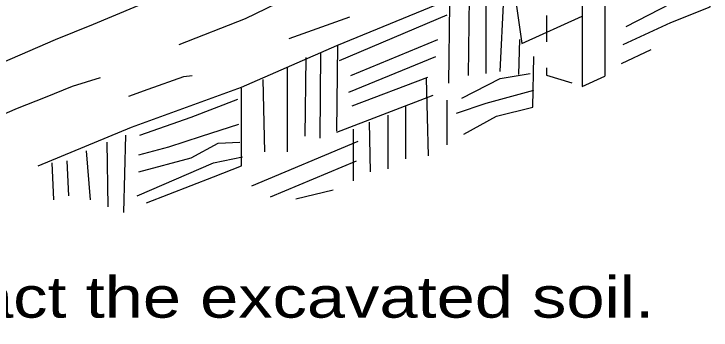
# Model space of a CAD drawing. Extents: x 1083.1 to 1117.1, y 672.5 to 716.5.
# Drawn here: x 1109.933 to 1112.582, y 688.724 to 689.926 of the extents above; entities that cross this region are included whole.
import ezdxf
from ezdxf.enums import TextEntityAlignment as Align

# ---------------------------------------------------------------- set-up
doc = ezdxf.new("R2010")
doc.units = 0
doc.header["$LTSCALE"] = 0.062
doc.linetypes.add('DOTTED', pattern=[1.5, 0.3, -1.2])
doc.layers.add('1', color=7, linetype='Continuous', lineweight=13)

msp = doc.modelspace()

# ---------------------------------------------------------------- linework, layer by layer
at = {"layer": '1', "lineweight": 25}
for p, q in [((1112.17775, 692.14508), (1112.17775, 689.6895)), ((1112.09242, 692.13417), (1112.09242, 689.65067)), ((1111.78075, 689.7075), (1111.7985, 690.07067)), ((1111.7275, 689.69992), (1111.7275, 690.029)), ((1112.259, 689.87767), (1112.57117, 690.04033)), ((1111.66017, 689.69242), (1111.66367, 690.00258)), ((1111.58567, 689.66217), (1111.58917, 689.96475)), ((1111.17067, 689.74917), (1111.57858, 689.92308)), ((1110.97917, 689.83233), (1111.20967, 689.91558)), ((1111.21325, 689.69242), (1111.54308, 689.82858)), ((1111.85167, 689.69617), (1111.85525, 689.82858)), ((1111.16, 689.48058), (1111.16358, 689.80583)), ((1112.24125, 689.73775), (1112.35475, 689.79067)), ((1111.03942, 689.46167), (1111.043, 689.7605)), ((1111.09617, 689.45408), (1111.09975, 689.77942)), ((1111.20617, 689.62808), (1111.536, 689.76425)), ((1111.90492, 689.57133), (1111.90842, 689.76425)), ((1110.972, 689.40117), (1110.972, 689.72267)), ((1111.50408, 689.68483), (1111.21675, 689.57517)), ((1111.50767, 689.386), (1111.5005, 689.68108)), ((1112.09242, 689.65067), (1112.17775, 689.6895)), ((1110.88692, 689.40117), (1110.87983, 689.67725)), ((1111.16, 689.47683), (1111.52533, 689.61675)), ((1111.4225, 689.37467), (1111.4225, 689.57517)), ((1111.57858, 689.42767), (1111.57858, 689.59783)), ((1111.35508, 689.33683), (1111.35508, 689.54108)), ((1111.28775, 689.3255), (1111.28417, 689.51458)), ((1111.22383, 689.2915), (1111.22383, 689.48817)), ((1110.35133, 689.17042), (1110.35842, 689.46542)), ((1110.83725, 689.27258), (1111.24158, 689.44275)), ((1110.291, 689.19308), (1110.2875, 689.439)), ((1110.22367, 689.21958), (1110.20942, 689.40492)), ((1110.14208, 689.23475), (1110.13492, 689.36708)), ((1110.90817, 689.23092), (1111.2345, 689.36708)), ((1110.08533, 689.21958), (1110.07817, 689.35958)), ((1111.00392, 689.22342), (1111.14583, 689.25742))]:
    msp.add_line(p, q, dxfattribs=at)
at = {"layer": '1', "linetype": 'DOTTED', "lineweight": 25}
for p, q in [((1111.95708, 690.3205), (1111.95708, 689.69367)), ((1111.95708, 689.69367), (1112.09242, 689.65067))]:
    msp.add_line(p, q, dxfattribs=at)
at = {"layer": '1', "lineweight": 25}
for points in [[(1110.025, 689.34817), (1110.37967, 689.49575), (1110.79825, 689.647), (1111.16, 689.80583), (1111.58917, 689.98367), (1111.81625, 690.07817)], [(1111.82333, 690.0895), (1111.86233, 689.81342), (1112.09242, 689.91692)], [(1112.24833, 689.80958), (1112.42925, 689.89283), (1112.57825, 689.95333), (1112.58175, 690.09325)], [(1109.7835, 689.69625), (1110.09158, 689.82917), (1110.23508, 689.88683), (1110.64433, 690.05992)], [(1110.56058, 689.80967), (1110.81242, 689.908), (1110.972, 689.98742), (1111.10325, 690.02142)], [(1109.84058, 689.52217), (1109.947, 689.56758), (1110.05342, 689.60917), (1110.15625, 689.65075), (1110.26267, 689.68483)], [(1110.36908, 689.613), (1110.4435, 689.63942), (1110.57833, 689.68858), (1110.61025, 689.69242)], [(1111.63533, 689.60542), (1111.78075, 689.68108), (1111.89425, 689.69992)], [(1110.43642, 689.20825), (1110.69183, 689.30658), (1110.79825, 689.34817), (1110.79825, 689.64325)], [(1111.614, 689.54867), (1111.7275, 689.5865), (1111.90842, 689.63567)], [(1110.41158, 689.46542), (1110.60667, 689.5335), (1110.78408, 689.60158)], [(1111.64242, 689.46925), (1111.76658, 689.53733), (1111.90492, 689.57133)], [(1110.40808, 689.38983), (1110.52158, 689.42008), (1110.64575, 689.46167), (1110.78758, 689.50708)], [(1110.40808, 689.3255), (1110.60667, 689.3785), (1110.70958, 689.43517), (1110.79117, 689.439)], [(1110.401, 689.23475), (1110.69183, 689.35958), (1110.80175, 689.38225)]]:
    msp.add_lwpolyline(points, dxfattribs=at)

# ---------------------------------------------------------------- texts
at = {"layer": '1', "width": 1.25}
msp.add_text('Backfill and compact the excavated soil.', height=0.156, dxfattribs=at).set_placement((1110.05363, 688.771), align=Align.CENTER)

doc.saveas('drawing.dxf')
